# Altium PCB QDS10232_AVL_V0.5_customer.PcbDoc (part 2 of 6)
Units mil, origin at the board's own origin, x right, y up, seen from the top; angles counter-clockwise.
Board outline 3500 x 3799 mil, 6 copper layers (Top Layer, GND, INT1, PWR1, PWR2, Bottom Layer), stack 78.834 mil thick; 254 components, 204 nets, 7039 pads, 595 vias.
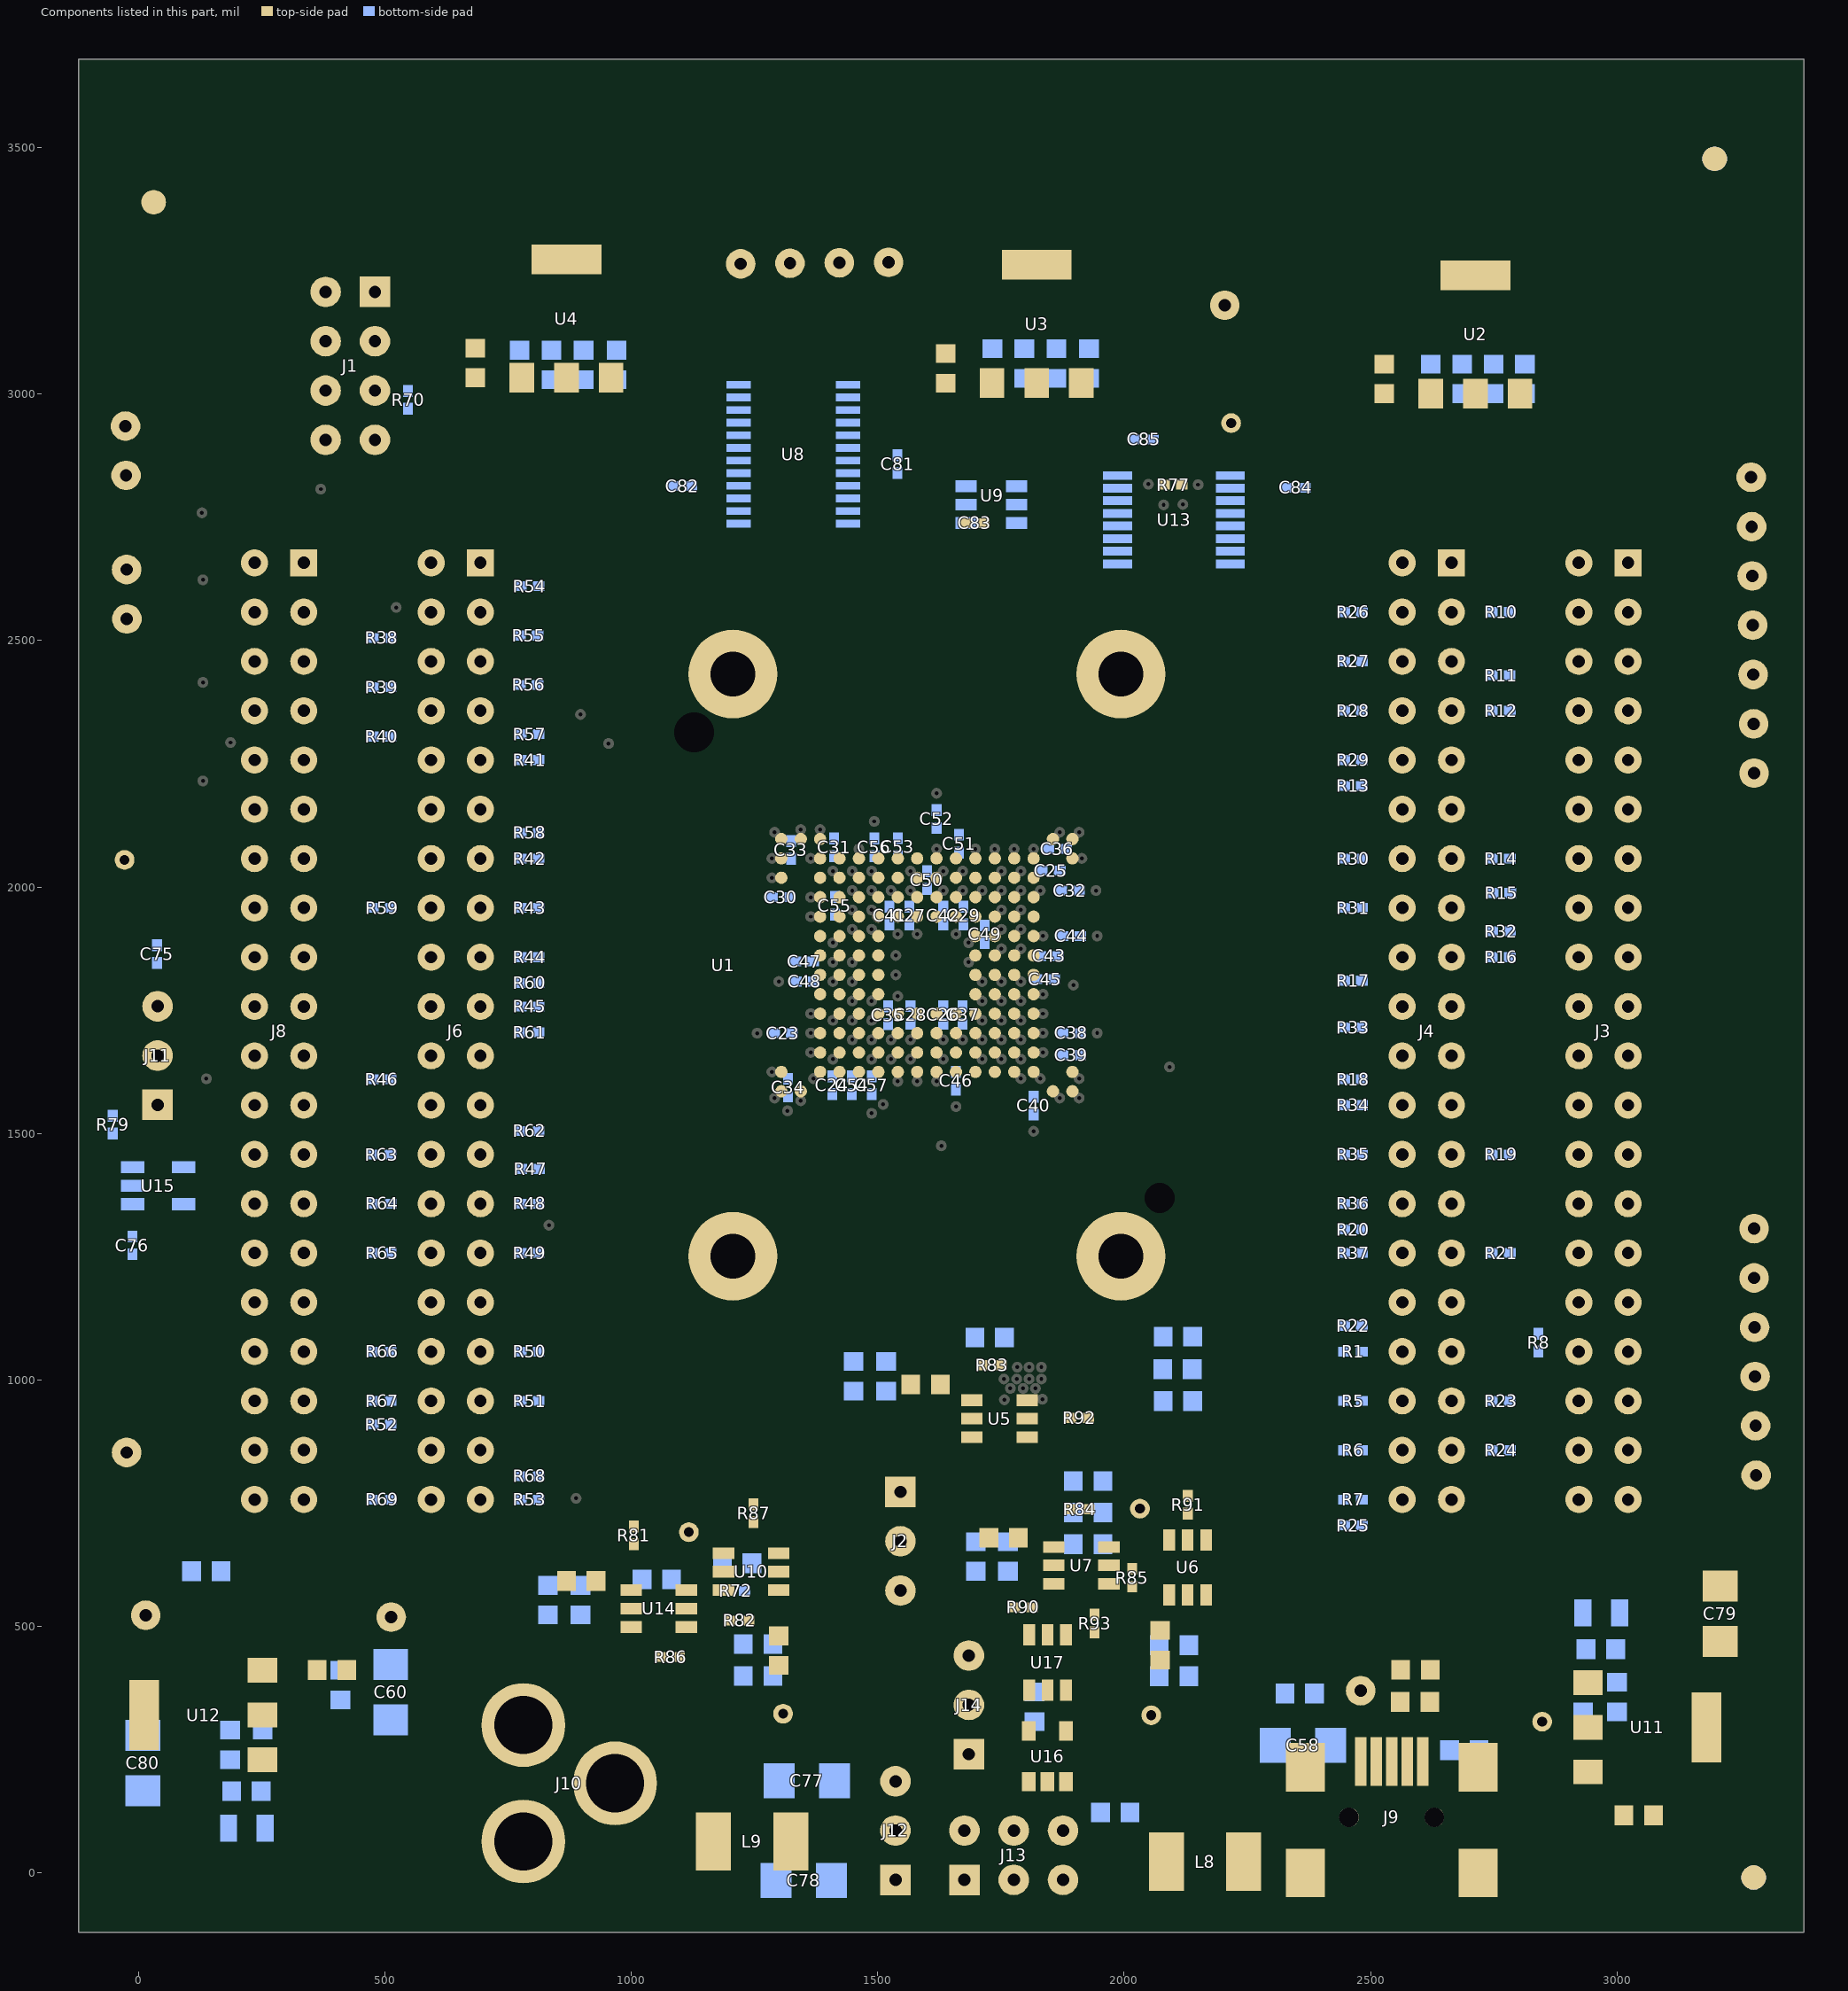
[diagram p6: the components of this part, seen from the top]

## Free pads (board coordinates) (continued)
  round 1.54 on Bottom Overlay: ""(2480.19,3556.7) ""(2480.19,3556.7) ""(2480.19,3556.7) ""(2480.19,3556.7) ""(2486.71,3556.7) ""(2486.71,3556.7) ""(2486.71,3556.7) ""(2486.71,3556.7) ""(2491.47,3556.5) ""(2491.47,3556.5) ""(2491.47,3556.5) ""(2491.47,3556.5) ""(2491.66,3570.83) ""(2491.66,3570.83) ""(2491.66,3570.83) ""(2491.66,3570.83) ""(2492,3569.15) ""(2492,3569.15) ""(2492,3569.15) ""(2492,3569.15) ""(2492.17,3555.54) ""(2492.17,3555.54) ""(2492.17,3555.54) ""(2492.17,3555.54) ""(2492.18,3557.16) ""(2492.18,3557.16) ""(2492.18,3557.16) ""(2492.18,3557.16) ""(2492.18,3572.37) ""(2492.18,3572.37) ""(2492.18,3572.37) ""(2492.18,3572.37) ""(2492.57,3568.58) ""(2492.57,3568.58) ""(2492.57,3568.58) ""(2492.57,3568.58) ""(2493.73,3555.94) ""(2493.73,3555.94) ""(2493.73,3555.94) ""(2493.73,3555.94) ""(2493.77,3554.22) ""(2493.77,3554.22) ""(2493.77,3554.22) ""(2493.77,3554.22) ""(2493.83,3568.07) ""(2493.83,3568.07) ""(2493.83,3568.07) ""(2493.83,3568.07) ""(2495.09,3568.24) ""(2495.09,3568.24) ""(2495.09,3568.24) ""(2495.09,3568.24) ""(2495.74,3554.88) ""(2495.74,3554.88) ""(2495.74,3554.88) ""(2495.74,3554.88) ""(2495.8,3574.68) ""(2495.8,3574.68) ""(2495.8,3574.68) ""(2495.8,3574.68) ""(2495.9,3571.78) ""(2495.9,3571.78) ""(2495.9,3571.78) ""(2495.9,3571.78) ""(2496.01,3568.7) ""(2496.01,3568.7) ""(2496.01,3568.7) ""(2496.01,3568.7) ""(2496.07,3573.19) ""(2496.07,3573.19) ""(2496.08,3573.19) ""(2496.08,3573.19) ""(2496.27,3553.55) ""(2496.27,3553.55) ""(2496.27,3553.55) ""(2496.27,3553.55) ""(2496.38,3570.95) ""(2496.38,3570.95) ""(2496.38,3570.95) ""(2496.38,3570.95) ""(2496.54,3569.84) ""(2496.54,3569.84) ""(2496.54,3569.84) ""(2496.54,3569.84) ""(2497.13,3574.07) ""(2497.13,3574.07) ""(2497.13,3574.07) ""(2497.13,3574.07) ""(2497.72,3554.75) ""(2497.72,3554.75) ""(2497.72,3554.75) ""(2497.72,3554.75) ""(2498.86,3553.55) ""(2498.86,3553.55) ""(2498.86,3553.55) ""(2498.86,3553.55) ""(2498.91,3574.21) ""(2498.91,3574.21) ""(2498.91,3574.21) ""(2498.91,3574.21) ""(2499.74,3574.98) ""(2499.74,3574.98) ""(2499.74,3574.98) ""(2499.74,3574.98) ""(2500.16,3555.36) ""(2500.16,3555.36) ""(2500.16,3555.36) ""(2500.16,3555.36) ""(2500.48,3573.68) ""(2500.48,3573.68) ""(2500.48,3573.68) ""(2500.48,3573.68) ""(2501.84,3572.45) ""(2501.84,3572.45) ""(2501.84,3572.45) ""(2501.84,3572.45) ""(2502.2,3557.4) ""(2502.2,3557.4) ""(2502.2,3557.4) ""(2502.2,3557.4) ""(2502.24,3554.06) ""(2502.24,3554.06) ""(2502.24,3554.06) ""(2502.24,3554.06) ""(2503.13,3574.48) ""(2503.13,3574.48) ""(2503.13,3574.48) ""(2503.13,3574.48) ""(2503.23,3570.37) ""(2503.23,3570.37) ""(2503.23,3570.37) ""(2503.23,3570.37) ""(2503.57,3560.03) ""(2503.57,3560.03) ""(2503.57,3560.03) ""(2503.57,3560.03) ""(2504.35,3563.71) ""(2504.35,3563.71) ""(2504.35,3563.71) ""(2504.35,3563.71) ""(2504.35,3566.77) ""(2504.35,3566.77) ""(2504.35,3566.77) ""(2504.35,3566.77) ""(2504.99,3554.94) ""(2504.99,3554.94) ""(2504.99,3554.94) ""(2504.99,3554.94) ""(2506.76,3556.52) ""(2506.76,3556.52) ""(2506.76,3556.52) ""(2506.76,3556.52) ""(2506.82,3572.59) ""(2506.82,3572.59) ""(2506.82,3572.59) ""(2506.82,3572.59) ""(2508.46,3558.21) ""(2508.46,3558.21) ""(2508.46,3558.21) ""(2508.46,3558.21) ""(2508.7,3570.51) ""(2508.7,3570.51) ""(2508.7,3570.51) ""(2508.7,3570.51) ""(2508.82,3570.34) ""(2508.82,3570.34) ""(2508.82,3570.34) ""(2508.82,3570.34) ""(2509.82,3560.93) ""(2509.82,3560.93) ""(2509.82,3560.93) ""(2509.82,3560.93) ""(2510.12,3564.6) ""(2510.12,3564.6) ""(2510.12,3564.6) ""(2510.12,3564.6) ""(2513.7,3554.18) ""(2513.7,3554.18) ""(2513.7,3554.56) ""(2513.7,3554.56) ""(2513.7,3554.18) ""(2513.7,3554.18) ""(2513.7,3554.56) ""(2513.7,3554.56) ""(2516.13,3556.89) ""(2516.13,3556.89) ""(2516.13,3568.58) ""(2516.13,3568.58) ""(2516.72,3571.52) ""(2516.72,3571.52) ""(2516.72,3571.52) ""(2516.72,3571.52) ""(2518,3573.35) ""(2518,3573.35) ""(2518.01,3573.35) ""(2518.01,3573.35) ""(2519.75,3574.27) ""(2519.75,3574.27) ""(2519.75,3574.27) ""(2519.75,3574.27) ""(2522.01,3557.33) ""(2522.01,3557.33) ""(2522.01,3570.41) ""(2522.01,3570.41) ""(2522.01,3557.33) ""(2522.01,3557.33) ""(2522.01,3570.41) ""(2522.01,3570.41) ""(2522.94,3572.41) ""(2522.94,3572.41) ""(2522.94,3572.41) ""(2522.94,3572.41) ""(2522.94,3574.87) ""(2522.94,3574.87) ""(2522.94,3574.87) ""(2522.94,3574.87) ""(2524.13,3554.18) ""(2524.13,3554.18) ""(2524.13,3554.18) ""(2524.13,3554.18) ""(2524.13,3555.08) ""(2524.13,3555.08) ""(2524.13,3555.08) ""(2524.13,3555.08) ""(2525.01,3573.38) ""(2525.01,3573.38) ""(2525.01,3573.38) ""(2525.01,3573.38) ""(2525.34,3574.77) ""(2525.34,3574.77) ""(2525.34,3574.77) ""(2525.34,3574.77) ""(2526.92,3573) ""(2526.92,3573) ""(2526.92,3573) ""(2526.92,3573) ""(2526.94,3554.18) ""(2526.94,3554.18) ""(2526.94,3554.18) ""(2526.94,3554.18) ""(2526.94,3555.03) ""(2526.94,3555.03) ""(2526.94,3555.03) ""(2526.94,3555.03) ""(2527.23,3573.83) ""(2527.23,3573.83) ""(2527.23,3573.83) ""(2527.23,3573.83) ""(2528.53,3572.38) ""(2528.53,3572.38) ""(2529.59,3557.36) ""(2529.59,3557.36) ""(2529.59,3557.36) ""(2529.59,3557.36) ""(2529.59,3571.17) ""(2529.59,3571.17) ""(2529.59,3571.17) ""(2529.59,3571.17) ""(2530.12,3571.48) ""(2530.12,3571.48) ""(2530.12,3571.48) ""(2530.12,3571.48) ""(2530.12,3574.66) ""(2530.12,3574.66) ""(2530.12,3574.66) ""(2530.12,3574.66) ""(2535.47,3557.17) ""(2535.47,3557.17) ""(2535.47,3557.17) ""(2535.47,3557.17) ""(2535.47,3571.11) ""(2535.47,3571.11) ""(2535.47,3571.11) ""(2535.47,3571.11) ""(2537.9,3554.18) ""(2537.9,3554.18) ""(2537.9,3554.18) ""(2537.9,3554.18) ""(2537.9,3555.16) ""(2537.9,3555.16) ""(2537.9,3555.16) ""(2537.9,3555.16) ""(2537.9,3573.34) ""(2537.9,3573.34) ""(2537.9,3573.34) ""(2537.9,3573.34) ""(2537.9,3574.66) ""(2537.9,3574.66) ""(2537.9,3574.66) ""(2537.9,3574.66) ""(2541.46,3554.18) ""(2541.46,3554.18) ""(2541.46,3554.76) ""(2541.46,3554.76) ""(2541.46,3554.18) ""(2541.46,3554.18) ""(2541.46,3554.76) ""(2541.46,3554.76) ""(2541.67,3582.88) ""(2541.67,3582.88) ""(2541.67,3583.77) ""(2541.67,3583.77) ""(2541.67,3582.88) ""(2541.67,3582.88) ""(2541.67,3583.77) ""(2541.67,3583.77) ""(2550.41,3556.3) ""(2550.41,3556.3) ""(2550.41,3556.3) ""(2550.41,3556.3) ""(2550.41,3581.09) ""(2550.41,3581.09) ""(2550.41,3581.09) ""(2550.41,3581.09) ""(2552.85,3554.18) ""(2552.85,3554.18) ""(2552.85,3554.5) ""(2552.85,3554.5) ""(2552.85,3583.1) ""(2552.85,3583.1) ""(2552.85,3583.77) ""(2552.85,3583.77) ""(2552.85,3554.18) ""(2552.85,3554.18) ""(2552.85,3554.5) ""(2552.85,3554.5) ""(2552.85,3583.1) ""(2552.85,3583.1) ""(2552.85,3583.77) ""(2552.85,3583.77) ""(2560.65,3555.44) ""(2560.65,3555.44) ""(2560.65,3555.44) ""(2560.65,3555.44) ""(2560.75,3553.91) ""(2560.75,3553.91) ""(2560.75,3553.91) ""(2560.75,3553.91) ""(2560.99,3557.24) ""(2560.99,3557.24) ""(2560.99,3557.24) ""(2560.99,3557.24) ""(2561.4,3551.62) ""(2561.4,3551.62) ""(2561.4,3551.62) ""(2561.4,3551.62) ""(2561.55,3558.55) ""(2561.55,3558.55) ""(2561.55,3558.55) ""(2561.55,3558.55) ""(2562.24,3559.32) ""(2562.24,3559.32) ""(2562.24,3559.32) ""(2562.24,3559.32) ""(2562.34,3552.12) ""(2562.34,3552.12) ""(2562.34,3552.12) ""(2562.34,3552.12) ""(2562.68,3553.7) ""(2562.68,3553.7) ""(2562.68,3553.7) ""(2562.68,3553.7) ""(2562.75,3549.22) ""(2562.75,3549.22) ""(2562.75,3549.22) ""(2562.75,3549.22) ""(2562.83,3550.79) ""(2562.83,3550.79) ""(2562.83,3550.79) ""(2562.83,3550.79) ""(2562.9,3559.89) ""(2562.9,3559.89) ""(2562.9,3559.89) ""(2562.9,3559.89) ""(2563.47,3560.11) ""(2563.47,3560.11) ""(2563.47,3560.11) ""(2563.47,3560.11) ""(2563.69,3549.68) ""(2563.69,3549.68) ""(2563.69,3549.68) ""(2563.69,3549.68) ""(2564.14,3547.73) ""(2564.14,3547.73) ""(2564.14,3547.73) ""(2564.14,3547.73) ""(2564.35,3560.06) ""(2564.35,3560.06) ""(2564.35,3560.06) ""(2564.35,3560.06) ""(2565.22,3553.82) ""(2565.22,3553.82) ""(2565.22,3553.82) ""(2565.22,3553.82) ""(2565.3,3560.06) ""(2565.3,3560.06) ""(2565.3,3560.06) ""(2565.3,3560.06) ""(2565.3,3548.18) ""(2565.3,3548.18) ""(2565.3,3548.18) ""(2565.3,3548.18) ""(2565.59,3546.59) ""(2565.59,3546.59) ""(2565.59,3546.59) ""(2565.59,3546.59) ""(2565.84,3554.2) ""(2565.84,3554.2) ""(2565.84,3554.2) ""(2565.84,3554.2) ""(2565.92,3559.73) ""(2565.92,3559.73) ""(2565.92,3559.73) ""(2565.92,3559.73) ""(2566.33,3547.32) ""(2566.33,3547.32) ""(2566.33,3547.32) ""(2566.33,3547.32) ""(2566.45,3554.71) ""(2566.45,3554.71) ""(2566.45,3554.71) ""(2566.45,3554.71) ""(2566.54,3559.38) ""(2566.54,3559.38) ""(2566.54,3559.38) ""(2566.54,3559.38) ""(2566.94,3555.24) ""(2566.94,3555.24) ""(2566.94,3555.24) ""(2566.94,3555.24) ""(2566.96,3558.89) ""(2566.96,3558.89) ""(2566.96,3558.89) ""(2566.96,3558.89) ""(2567.19,3556.05) ""(2567.19,3556.05) ""(2567.19,3556.05) ""(2567.19,3556.05) ""(2567.19,3558.27) ""(2567.19,3558.27) ""(2567.19,3558.27) ""(2567.19,3558.27) ""(2567.23,3557.1) ""(2567.23,3557.1) ""(2567.23,3557.1) ""(2567.23,3557.1) ""(2573.55,3561.66) ""(2573.55,3561.66) ""(2573.55,3561.66) ""(2573.55,3561.66) ""(2573.62,3560.15) ""(2573.62,3560.15) ""(2573.62,3560.15) ""(2573.62,3560.15) ""(2573.82,3562.96) ""(2573.82,3562.96) ""(2573.82,3562.96) ""(2573.82,3562.96) ""(2574.23,3564.06) ""(2574.23,3564.06) ""(2574.23,3564.06) ""(2574.23,3564.06) ""(2574.3,3558.29) ""(2574.3,3558.29) ""(2574.3,3558.29) ""(2574.3,3558.29) ""(2574.3,3570.39) ""(2574.3,3570.39) ""(2574.3,3570.39) ""(2574.3,3570.39) ""(2574.3,3571.49) ""(2574.3,3571.49) ""(2574.3,3571.49) ""(2574.3,3571.49) ""(2574.51,3572.52) ""(2574.51,3572.52) ""(2574.58,3569.84) ""(2574.58,3569.84) ""(2574.58,3569.84) ""(2574.58,3569.84) ""(2574.65,3564.81) ""(2574.65,3564.81) ""(2574.65,3564.81) ""(2574.65,3564.81) ""(2574.99,3569.29) ""(2574.99,3569.29) ""(2574.99,3569.29) ""(2574.99,3569.29) ""(2575.06,3557.13) ""(2575.06,3557.13) ""(2575.06,3557.13) ""(2575.06,3557.13) ""(2575.13,3573.34) ""(2575.13,3573.34) ""(2575.13,3573.34) ""(2575.13,3573.34) ""(2575.61,3565.64) ""(2575.61,3565.64) ""(2575.61,3565.64) ""(2575.61,3565.64) ""(2575.95,3568.74) ""(2575.95,3568.74) ""(2576.02,3574.09) ""(2576.02,3574.09) ""(2576.09,3556.17) ""(2576.09,3556.17) ""(2576.09,3556.17) ""(2576.09,3556.17) ""(2576.85,3568.4) ""(2576.85,3568.4) ""(2576.85,3568.4) ""(2576.85,3568.4) ""(2577.33,3574.85) ""(2577.33,3574.85) ""(2577.33,3574.85) ""(2577.33,3574.85) ""(2577.4,3566.46) ""(2577.4,3566.46) ""(2577.4,3566.46) ""(2577.4,3566.46) ""(2577.74,3555.14) ""(2577.74,3555.14) ""(2577.74,3555.14) ""(2577.74,3555.14) ""(2578.15,3575.12) ""(2578.15,3575.12) ""(2578.15,3575.12) ""(2578.15,3575.12) ""(2579.04,3554.45) ""(2579.04,3554.45) ""(2579.04,3554.45) ""(2579.04,3554.45) ""(2579.25,3567.22) ""(2579.25,3567.22) ""(2579.25,3567.22) ""(2579.25,3567.22) ""(2579.32,3558.79) ""(2579.32,3558.79) ""(2579.32,3558.79) ""(2579.32,3558.79) ""(2579.32,3568.59) ""(2579.32,3568.59) ""(2579.32,3568.59) ""(2579.32,3568.59) ""(2579.46,3558.1) ""(2579.46,3558.1) ""(2579.46,3559.61) ""(2579.46,3559.61) ""(2579.46,3558.1) ""(2579.46,3558.1) ""(2579.46,3559.61) ""(2579.46,3559.61) ""(2579.66,3557.62) ""(2579.66,3557.62) ""(2579.66,3557.62) ""(2579.66,3557.62) ""(2579.73,3560.16) ""(2579.73,3560.16) ""(2579.73,3560.16) ""(2579.73,3560.16) ""(2579.73,3575.4) ""(2579.73,3575.4) ""(2579.73,3575.4) ""(2579.73,3575.4) ""(2579.87,3569.07) ""(2579.87,3569.07) ""(2579.87,3569.07) ""(2579.87,3569.07) ""(2579.87,3571.27) ""(2579.87,3571.27) ""(2579.87,3571.27) ""(2579.87,3571.27) ""(2579.87,3571.47) ""(2579.87,3571.47) ""(2579.87,3571.47) ""(2579.87,3571.47) ""(2580.01,3570.79) ""(2580.01,3570.79) ""(2580.01,3570.79) ""(2580.01,3570.79) ""(2580.01,3571.88) ""(2580.01,3571.88) ""(2580.01,3571.88) ""(2580.01,3571.88) ""(2580.07,3569.62) ""(2580.07,3569.62) ""(2580.07,3569.62) ""(2580.07,3569.62) ""(2580.14,3570.3) ""(2580.14,3570.3) ""(2580.14,3570.3) ""(2580.14,3570.3) ""(2580.14,3571.95) ""(2580.14,3571.95) ""(2580.14,3571.95) ""(2580.14,3571.95) ""(2580.28,3557.14) ""(2580.28,3557.14) ""(2580.28,3557.14) ""(2580.28,3557.14) ""(2580.42,3560.64) ""(2580.42,3560.64) ""(2580.42,3560.64) ""(2580.42,3560.64) ""(2580.49,3572.3) ""(2580.49,3572.3) ""(2580.49,3572.3) ""(2580.49,3572.3) ""(2580.69,3567.7) ""(2580.69,3567.7) ""(2580.69,3567.7) ""(2580.69,3567.7) ""(2580.9,3556.8) ""(2580.9,3556.8) ""(2580.9,3556.8) ""(2580.9,3556.8) ""(2581.24,3561.05) ""(2581.24,3561.05) ""(2581.24,3572.5) ""(2581.24,3572.5) ""(2581.52,3575.33) ""(2581.52,3575.33) ""(2581.52,3575.33) ""(2581.52,3575.33) ""(2582.14,3572.57) ""(2582.14,3572.57) ""(2582.14,3572.57) ""(2582.14,3572.57) ""(2582.2,3568.25) ""(2582.2,3568.25) ""(2582.2,3568.25) ""(2582.2,3568.25) ""(2582.27,3556.38) ""(2582.27,3556.38) ""(2582.27,3556.38) ""(2582.27,3556.38) ""(2582.96,3553.97) ""(2582.96,3553.97) ""(2582.96,3553.97) ""(2582.96,3553.97) ""(2583.03,3572.57) ""(2583.03,3572.57) ""(2583.03,3572.57) ""(2583.03,3572.57) ""(2583.17,3575.12) ""(2583.17,3575.12) ""(2583.17,3575.12) ""(2583.17,3575.12) ""(2583.37,3556.25) ""(2583.37,3556.25) ""(2583.37,3568.73) ""(2583.37,3568.73) ""(2583.85,3572.16) ""(2583.85,3572.16) ""(2583.85,3572.16) ""(2583.85,3572.16) ""(2584.06,3569) ""(2584.06,3569) ""(2584.06,3569) ""(2584.06,3569) ""(2584.26,3571.68) ""(2584.26,3571.68) ""(2584.26,3571.68) ""(2584.26,3571.68) ""(2584.4,3569.48) ""(2584.4,3569.48) ""(2584.4,3569.48) ""(2584.4,3569.48) ""(2584.47,3556.32) ""(2584.47,3556.32) ""(2584.47,3556.32) ""(2584.47,3556.32) ""(2584.54,3570.03) ""(2584.54,3570.03) ""(2584.54,3570.03) ""(2584.54,3570.03) ""(2584.54,3570.65) ""(2584.54,3570.65) ""(2584.54,3570.65) ""(2584.54,3570.65) ""(2584.81,3559.41) ""(2584.81,3559.41) ""(2584.81,3559.41) ""(2584.81,3559.41) ""(2584.88,3558.58) ""(2584.88,3558.58) ""(2585.02,3560.16) ""(2585.02,3560.16) ""(2585.02,3560.16) ""(2585.02,3560.16) ""(2585.09,3558.17) ""(2585.09,3558.17) ""(2585.09,3558.17) ""(2585.09,3558.17) ""(2585.09,3574.64) ""(2585.09,3574.64) ""(2585.09,3574.64) ""(2585.09,3574.64) ""(2585.23,3554.11) ""(2585.23,3554.11) ""(2585.23,3554.11) ""(2585.23,3554.11) ""(2585.29,3556.45) ""(2585.29,3556.45) ""(2585.29,3558.1) ""(2585.29,3558.1) ""(2585.3,3556.45) ""(2585.3,3556.45) ""(2585.3,3558.1) ""(2585.3,3558.1) ""(2585.71,3557.69) ""(2585.71,3557.69) ""(2585.71,3557.69) ""(2585.71,3557.69) ""(2585.78,3556.8) ""(2585.78,3556.8) ""(2585.78,3556.8) ""(2585.78,3556.8) ""(2585.84,3557.14) ""(2585.84,3557.14) ""(2585.84,3557.14) ""(2585.84,3557.14) ""(2585.98,3560.85) ""(2585.98,3560.85) ""(2585.98,3560.85) ""(2585.98,3560.85) ""(2586.6,3573.96) ""(2586.6,3573.96) ""(2586.6,3573.96) ""(2586.6,3573.96) ""(2586.81,3561.26) ""(2586.81,3561.26) ""(2586.81,3561.26) ""(2586.81,3561.26) ""(2586.94,3554.38) ""(2586.94,3554.38) ""(2586.94,3554.38) ""(2586.94,3554.38) ""(2587.22,3563.59) ""(2587.22,3563.59) ""(2587.22,3563.59) ""(2587.22,3563.59) ""(2587.63,3561.33) ""(2587.63,3561.33) ""(2587.63,3561.33) ""(2587.63,3561.33) ""(2587.84,3573.2) ""(2587.84,3573.2) ""(2587.84,3573.2) ""(2587.84,3573.2) ""(2588.11,3554.72) ""(2588.11,3554.72) ""(2588.11,3554.72) ""(2588.11,3554.72) ""(2588.39,3564.42) ""(2588.39,3564.42) ""(2588.39,3564.42) ""(2588.39,3564.42) ""(2588.73,3572.31) ""(2588.73,3572.31) ""(2588.73,3572.31) ""(2588.73,3572.31) ""(2589,3561.19) ""(2589,3561.19) ""(2589,3561.19) ""(2589,3561.19) ""(2589.28,3565.24) ""(2589.28,3565.24) ""(2589.28,3565.24) ""(2589.28,3565.24) ""(2589.35,3555.48) ""(2589.35,3555.48) ""(2589.35,3555.48) ""(2589.35,3555.48) ""(2589.35,3571.42) ""(2589.35,3571.42) ""(2589.35,3571.42) ""(2589.35,3571.42) ""(2589.62,3560.78) ""(2589.62,3560.78) ""(2589.62,3560.78) ""(2589.62,3560.78) ""(2589.9,3556.11) ""(2589.9,3556.11) ""(2589.9,3566.2) ""(2589.9,3566.2) ""(2589.9,3570.59) ""(2589.9,3570.59) ""(2589.9,3556.11) ""(2589.9,3556.11) ""(2589.9,3566.2) ""(2589.9,3566.2) ""(2589.9,3570.59) ""(2589.9,3570.59) ""(2590.17,3569.77) ""(2590.17,3569.77) ""(2590.17,3569.77) ""(2590.17,3569.77) ""(2590.24,3567.3) ""(2590.24,3567.3) ""(2590.24,3567.3) ""(2590.24,3567.3) ""(2590.31,3568.67) ""(2590.31,3568.67) ""(2590.31,3568.67) ""(2590.31,3568.67) ""(2590.38,3556.93) ""(2590.38,3556.93) ""(2590.38,3556.93) ""(2590.38,3556.93) ""(2590.38,3560.16) ""(2590.38,3560.16) ""(2590.38,3560.16) ""(2590.38,3560.16) ""(2590.65,3559.47) ""(2590.65,3559.47) ""(2590.65,3559.47) ""(2590.65,3559.47) ""(2590.72,3557.83) ""(2590.72,3557.83) ""(2590.72,3557.83) ""(2590.72,3557.83) ""(2590.79,3558.72) ""(2590.79,3558.72) ""(2590.79,3558.72) ""(2590.79,3558.72) ""(2593.72,3565.13) ""(2593.72,3566.01) ""(2593.72,3566.01) ""(2593.72,3565.13) ""(2593.72,3565.13) ""(2593.72,3565.13) ""(2593.72,3566.01) ""(2593.72,3566.01) ""(2593.72,3565.13) ""(2593.93,3567.59) ""(2593.93,3567.59) ""(2593.93,3567.59) ""(2593.93,3567.59) ""(2594,3557.35) ""(2594,3557.35) ""(2594,3557.35) ""(2594,3557.35) ""(2594,3557.35) ""(2594.08,3558.45) ""(2594.08,3558.45) ""(2594.08,3558.45) ""(2594.08,3558.45) ""(2594.08,3558.45) ""(2594.13,3568.75) ""(2594.13,3568.75) ""(2594.13,3568.75) ""(2594.13,3568.75) ""(2594.49,3564.36) ""(2594.49,3564.36) ""(2594.49,3564.36) ""(2594.49,3564.36) ""(2594.49,3564.36) ""(2594.88,3559.12) ""(2594.88,3559.12) ""(2594.88,3559.12) ""(2594.88,3559.12) ""(2594.88,3559.12) ""(2594.89,3556.33) ""(2594.89,3556.33) ""(2594.89,3556.33) ""(2594.89,3556.33) ""(2594.89,3570.4) ""(2594.89,3570.4) ""(2594.89,3570.4) ""(2594.89,3570.4) ""(2595.78,3555.44) ""(2595.78,3555.44) ""(2595.78,3571.84) ""(2595.78,3571.84) ""(2595.78,3555.44) ""(2595.78,3555.44) ""(2595.78,3571.84) ""(2595.78,3571.84) ""(2595.92,3559.07) ""(2595.92,3559.07) ""(2595.92,3559.07) ""(2595.92,3559.07) ""(2595.92,3559.07) ""(2596.47,3558.53) ""(2596.47,3558.53) ""(2596.81,3572.87) ""(2596.81,3572.87) ""(2596.81,3572.87) ""(2596.81,3572.87) ""(2597.36,3554.48) ""(2597.36,3554.48) ""(2597.36,3554.48) ""(2597.36,3554.48) ""(2597.57,3557.7) ""(2597.57,3557.7) ""(2597.57,3557.7) ""(2597.57,3557.7) ""(2598.12,3573.9) ""(2598.12,3573.9) ""(2598.12,3573.9) ""(2598.12,3573.9) ""(2598.46,3554) ""(2598.46,3554) ""(2598.46,3554) ""(2598.46,3554) ""(2598.53,3557.08) ""(2598.53,3557.08) ""(2598.53,3557.08) ""(2598.53,3557.08) ""(2599.28,3574.66) ""(2599.28,3574.66) ""(2599.28,3574.66) ""(2599.28,3574.66) ""(2599.7,3556.6) ""(2599.7,3556.6) ""(2599.7,3556.6) ""(2599.7,3556.6) ""(2600.18,3567.46) ""(2600.18,3568.07) ""(2600.18,3568.07) ""(2600.18,3567.46) ""(2600.18,3567.46) ""(2600.18,3567.46) ""(2600.18,3567.46) ""(2600.18,3568.07) ""(2600.18,3568.07) ""(2600.32,3569.51) ""(2600.32,3569.51) ""(2600.32,3569.51) ""(2600.32,3569.51) ""(2600.52,3570.61) ""(2600.52,3570.61) ""(2600.52,3570.61) ""(2600.52,3570.61) ""(2600.65,3575.14) ""(2600.65,3575.14) ""(2600.65,3575.14) ""(2600.65,3575.14) ""(2600.73,3553.79) ""(2600.73,3553.79) ""(2600.73,3553.79) ""(2600.73,3553.79) ""(2600.87,3571.36) ""(2600.87,3571.36) ""(2600.87,3571.36) ""(2600.87,3571.36) ""(2600.95,3566.69) ""(2600.95,3566.69) ""(2600.95,3566.69) ""(2600.95,3566.69) ""(2600.95,3566.69) ""(2601,3556.47) ""(2601,3556.47) ""(2601,3556.47) ""(2601,3556.47) ""(2601.55,3572.05) ""(2601.55,3572.05) ""(2601.55,3572.05) ""(2601.55,3572.05) ""(2601.96,3556.54) ""(2601.96,3556.54) ""(2601.96,3556.54) ""(2601.96,3556.54) ""(2602.23,3575.35) ""(2602.23,3575.35) ""(2602.31,3572.32) ""(2602.31,3572.32) ""(2602.31,3572.32) ""(2602.31,3572.32) ""(2602.79,3553.79) ""(2602.79,3553.79) ""(2602.93,3556.81) ""(2602.93,3556.81) ""(2602.93,3556.81) ""(2602.93,3556.81) ""(2602.99,3572.39) ""(2602.99,3572.39) ""(2602.99,3572.39) ""(2602.99,3572.39) ""(2603.54,3575.35) ""(2603.54,3575.35) ""(2603.54,3575.35) ""(2603.54,3575.35) ""(2603.68,3557.15) ""(2603.68,3557.15) ""(2603.68,3557.15) ""(2603.68,3557.15) ""(2603.89,3572.32) ""(2603.89,3572.32) ""(2603.89,3572.32) ""(2603.89,3572.32) ""(2604.85,3558.18) ""(2604.85,3558.18) ""(2604.85,3558.18) ""(2604.85,3558.18) ""(2605.26,3554) ""(2605.26,3554) ""(2605.26,3558.8) ""(2605.26,3558.8) ""(2605.26,3554) ""(2605.26,3554) ""(2605.26,3558.8) ""(2605.26,3558.8) ""(2605.47,3571.16) ""(2605.47,3571.16) ""(2605.47,3571.16) ""(2605.47,3571.16) ""(2605.49,3566.69) ""(2605.49,3566.69) ""(2605.49,3566.69) ""(2605.49,3566.69) ""(2605.49,3566.69) ""(2605.59,3564.36) ""(2605.59,3564.36) ""(2605.59,3564.36) ""(2605.59,3564.36) ""(2605.59,3564.36) ""(2605.67,3575.21) ""(2605.67,3575.21) ""(2605.67,3575.21) ""(2605.67,3575.21) ""(2605.74,3570.47) ""(2605.74,3570.47) ""(2605.74,3570.47) ""(2605.74,3570.47) ""(2605.81,3560.24) ""(2605.81,3560.24) ""(2605.81,3560.24) ""(2605.81,3560.24) ""(2606.02,3561.07) ""(2606.02,3561.07) ""(2606.02,3561.07) ""(2606.02,3561.07) ""(2606.17,3569.09) ""(2606.17,3569.09) ""(2606.17,3569.09) ""(2606.17,3569.09) ""(2606.17,3569.09) ""(2606.2,3568.89) ""(2606.2,3568.89) ""(2606.2,3568.89) ""(2606.2,3568.89) ""(2606.2,3568.89) ""(2606.22,3562.16) ""(2606.22,3562.16) ""(2606.22,3562.16) ""(2606.22,3562.16) ""(2606.26,3567.49) ""(2606.26,3567.49) ""(2606.26,3567.49) ""(2606.26,3567.49) ""(2606.26,3567.49) ""(2606.36,3563.51) ""(2606.36,3563.51) ""(2606.36,3563.51) ""(2606.36,3563.51) ""(2606.36,3563.51) ""(2607.25,3554.61) ""(2607.25,3554.61) ""(2607.25,3554.61) ""(2607.25,3554.61) ""(2607.6,3574.31) ""(2607.6,3574.31) ""(2607.6,3574.31) ""(2607.6,3574.31) ""(2608.56,3555.23) ""(2608.56,3555.23) ""(2608.97,3573.35) ""(2608.97,3573.35) ""(2608.97,3573.35) ""(2608.97,3573.35) ""(2610.07,3572.39) ""(2610.07,3572.39) ""(2610.07,3572.39) ""(2610.07,3572.39) ""(2610.14,3556.33) ""(2610.14,3556.33) ""(2610.14,3556.33) ""(2610.14,3556.33) ""(2611.17,3571.22) ""(2611.17,3571.22) ""(2611.17,3571.22) ""(2611.17,3571.22) ""(2611.93,3569.99) ""(2611.93,3569.99) ""(2611.93,3569.99) ""(2611.93,3569.99) ""(2612.2,3559.01) ""(2612.2,3559.01) ""(2612.2,3559.01) ""(2612.2,3559.01) ""(2612.54,3568.62) ""(2612.54,3568.62) ""(2612.54,3568.62) ""(2612.54,3568.62) ""(2612.82,3560.45) ""(2612.82,3560.45) ""(2612.82,3560.45) ""(2612.82,3560.45) ""(2612.96,3567.45) ""(2612.96,3567.45) ""(2612.96,3567.45) ""(2612.96,3567.45) ""(2613.16,3562.37) ""(2613.16,3562.37) ""(2613.16,3562.37) ""(2613.16,3562.37) ""(2613.23,3566.01) ""(2613.23,3566.01) ""(2613.23,3566.01) ""(2613.23,3566.01) ""(2613.3,3564.09) ""(2613.3,3564.09) ""(2613.3,3564.09) ""(2613.3,3564.09) ""(2615.83,3557.63) ""(2615.83,3557.63) ""(2615.83,3557.63) ""(2615.83,3557.63) ""(2615.83,3557.63) ""(2615.85,3556.57) ""(2615.85,3556.57) ""(2615.85,3556.57) ""(2615.85,3556.57) ""(2615.85,3556.57) ""(2616.13,3569.71) ""(2616.13,3569.71) ""(2616.13,3569.71) ""(2616.13,3569.71) ""(2616.27,3571.42) ""(2616.27,3571.42) ""(2616.27,3571.42) ""(2616.27,3571.42) ""(2616.41,3568.68) ""(2616.41,3568.68) ""(2616.41,3568.68) ""(2616.41,3568.68) ""(2616.61,3555.77) ""(2616.61,3555.77) ""(2616.61,3555.77) ""(2616.61,3555.77) ""(2616.63,3558.5) ""(2616.63,3558.5) ""(2616.63,3558.5) ""(2616.63,3558.5) ""(2616.63,3558.5) ""(2616.68,3572.25) ""(2616.68,3572.25) ""(2616.68,3572.25) ""(2616.68,3572.25) ""(2617.09,3567.79) ""(2617.09,3567.79) ""(2617.09,3567.79) ""(2617.09,3567.79) ""(2617.3,3573.14) ""(2617.3,3573.14) ""(2617.3,3573.14) ""(2617.3,3573.14) ""(2617.51,3555.16) ""(2617.51,3555.16) ""(2617.51,3555.16) ""(2617.51,3555.16) ""(2617.69,3558.58) ""(2617.69,3558.58) ""(2617.69,3558.58) ""(2617.69,3558.58) ""(2617.69,3558.58) ""(2617.85,3567.44) ""(2617.85,3567.44) ""(2617.85,3567.44) ""(2617.85,3567.44) ""(2618.19,3573.89) ""(2618.19,3573.89) ""(2618.19,3573.89) ""(2618.19,3573.89) ""(2618.26,3558.11) ""(2618.26,3558.11) ""(2618.26,3558.11) ""(2618.26,3558.11) ""(2618.61,3567.17) ""(2618.61,3567.17) ""(2618.61,3567.17) ""(2618.61,3567.17) ""(2618.81,3554.47) ""(2618.81,3554.47) ""(2618.81,3554.47) ""(2618.81,3554.47) ""(2619.02,3574.44) ""(2619.02,3574.44) ""(2619.02,3574.44) ""(2619.02,3574.44) ""(2619.36,3557.42) ""(2619.36,3557.42) ""(2619.36,3557.42) ""(2619.36,3557.42) ""(2619.57,3567.03) ""(2619.57,3567.03) ""(2619.57,3567.03) ""(2619.57,3567.03) ""(2619.84,3554.2) ""(2619.84,3554.2) ""(2619.84,3554.2) ""(2619.84,3554.2) ""(2620.25,3574.79) ""(2620.25,3574.79) ""(2620.25,3574.79) ""(2620.25,3574.79) ""(2620.49,3567.1) ""(2620.49,3567.1) ""(2620.49,3567.1) ""(2620.49,3567.1) ""(2620.72,3567.2) ""(2620.72,3567.2) ""(2620.72,3567.2) ""(2620.72,3567.2) ""(2620.87,3571.32) ""(2620.87,3571.32) ""(2620.87,3571.32) ""(2620.87,3571.32) ""(2620.91,3571.12) ""(2620.91,3571.12) ""(2620.91,3571.12) ""(2620.91,3571.12) ""(2620.94,3556.73) ""(2620.94,3556.73) ""(2620.94,3556.73) ""(2620.94,3556.73) ""(2620.94,3571.66) ""(2620.94,3571.66) ""(2620.94,3571.66) ""(2620.94,3571.66) ""(2620.99,3570.94) ""(2620.99,3570.94) ""(2620.99,3570.94) ""(2620.99,3570.94) ""(2621.04,3571.85) ""(2621.04,3571.85) ""(2621.04,3571.85) ""(2621.04,3571.85) ""(2621.06,3567.5) ""(2621.06,3567.5) ""(2621.06,3567.5) ""(2621.06,3567.5) ""(2621.08,3554.13) ""(2621.08,3554.13) ""(2621.08,3554.13) ""(2621.08,3554.13) ""(2621.16,3570.77) ""(2621.16,3570.77) ""(2621.16,3570.77) ""(2621.16,3570.77) ""(2621.22,3572.04) ""(2621.22,3572.04) ""(2621.22,3572.04) ""(2621.22,3572.04) ""(2621.26,3567.79) ""(2621.26,3567.79) ""(2621.26,3567.79) ""(2621.26,3567.79) ""(2621.28,3570.63) ""(2621.28,3570.63) ""(2621.28,3570.63) ""(2621.28,3570.63) ""(2621.45,3570.38) ""(2621.45,3570.38) ""(2621.45,3570.38) ""(2621.45,3570.38) ""(2621.49,3568.13) ""(2621.49,3568.13) ""(2621.49,3568.13) ""(2621.49,3568.13) ""(2621.6,3570.1) ""(2621.6,3570.1) ""(2621.6,3570.1) ""(2621.6,3570.1) ""(2621.7,3568.75) ""(2621.7,3568.75) ""(2621.7,3568.75) ""(2621.7,3568.75) ""(2621.7,3574.99) ""(2621.7,3574.99) ""(2621.7,3574.99) ""(2621.7,3574.99) ""(2621.72,3569.67) ""(2621.72,3569.67) ""(2621.72,3569.67) ""(2621.72,3569.67) ""(2621.73,3569.2) ""(2621.73,3569.2) ""(2621.73,3569.2) ""(2621.73,3569.2) ""(2622.25,3556.6) ""(2622.25,3556.6) ""(2622.25,3556.6) ""(2622.25,3556.6) ""(2622.45,3572.45) ""(2622.45,3572.45) ""(2622.45,3572.45) ""(2622.45,3572.45) ""(2623.07,3556.73) ""(2623.07,3556.73) ""(2623.07,3556.73) ""(2623.07,3556.73) ""(2623.35,3572.38) ""(2623.35,3572.38) ""(2623.35,3572.38) ""(2623.35,3572.38) ""(2623.48,3554.13) ""(2623.48,3554.13) ""(2623.48,3574.99) ""(2623.48,3574.99) ""(2623.48,3554.13) ""(2623.48,3554.13) ""(2623.48,3574.99) ""(2623.48,3574.99) ""(2623.96,3556.94) ""(2623.96,3556.94) ""(2623.96,3556.94) ""(2623.96,3556.94) ""(2624.51,3572.04) ""(2624.51,3572.04) ""(2624.51,3572.04) ""(2624.51,3572.04) ""(2624.65,3557.42) ""(2624.65,3557.42) ""(2624.65,3557.42) ""(2624.65,3557.42) ""(2624.97,3554.09) ""(2624.97,3554.09) ""(2624.97,3554.09) ""(2624.97,3554.09) ""(2625.41,3557.97) ""(2625.41,3557.97) ""(2625.41,3574.85) ""(2625.41,3574.85) ""(2625.41,3557.97) ""(2625.41,3557.97) ""(2625.41,3574.85) ""(2625.41,3574.85) ""(2625.47,3571.29) ""(2625.47,3571.29) ""(2625.47,3571.29) ""(2625.47,3571.29) ""(2625.9,3554.16) ""(2625.9,3554.16) ""(2626.02,3558.79) ""(2626.02,3558.79) ""(2626.02,3558.79) ""(2626.02,3558.79) ""(2626.23,3570.19) ""(2626.23,3570.19) ""(2626.23,3570.19) ""(2626.23,3570.19) ""(2626.51,3559.76) ""(2626.51,3559.76) ""(2626.51,3559.76) ""(2626.51,3559.76) ""(2626.53,3554.31) ""(2626.53,3554.31) ""(2626.53,3554.31) ""(2626.53,3554.31) ""(2626.85,3568.75) ""(2626.85,3568.75) ""(2626.85,3568.75) ""(2626.85,3568.75) ""(2626.92,3561.06) ""(2626.92,3561.06) ""(2626.92,3561.06) ""(2626.92,3561.06) ""(2627.05,3567.65) ""(2627.05,3567.65) ""(2627.05,3567.65) ""(2627.05,3567.65) ""(2627.19,3566.28) ""(2627.19,3566.28) ""(2627.19,3566.28) ""(2627.19,3566.28) ""(2627.26,3562.64) ""(2627.26,3562.64) ""(2627.26,3562.64) ""(2627.26,3562.64) ""(2627.33,3564.35) ""(2627.33,3564.35) ""(2627.33,3564.35) ""(2627.33,3564.35) ""(2627.43,3554.63) ""(2627.43,3554.63) ""(2627.43,3554.63) ""(2627.43,3554.63) ""(2627.47,3574.44) ""(2627.47,3574.44) ""(2627.47,3574.44) ""(2627.47,3574.44) ""(2628.24,3555.08) ""(2628.24,3555.08) ""(2628.24,3555.08) ""(2628.24,3555.08) ""(2628.92,3555.5) ""(2628.92,3555.5) ""(2628.92,3555.5) ""(2628.92,3555.5) ""(2629.05,3573.69) ""(2629.05,3573.69) ""(2629.05,3573.69) ""(2629.05,3573.69) ""(2629.59,3556.04) ""(2629.59,3556.04) ""(2629.59,3556.04) ""(2629.59,3556.04) ""(2630.35,3572.59) ""(2630.35,3572.59) ""(2630.35,3572.59) ""(2630.35,3572.59) ""(2630.48,3556.74) ""(2630.48,3556.74) ""(2630.48,3556.74) ""(2630.48,3556.74) ""(2631.03,3557.26) ""(2631.03,3557.26) ""(2631.03,3557.26) ""(2631.03,3557.26) ""(2631.45,3557.7) ""(2631.45,3557.7) ""(2631.46,3557.7) ""(2631.46,3557.7) ""(2631.86,3571.29) ""(2631.86,3571.29) ""(2631.86,3571.29) ""(2631.86,3571.29) ""(2632,3558.38) ""(2632,3558.38) ""(2632,3558.38) ""(2632,3558.38) ""(2632.76,3569.91) ""(2632.76,3569.91) ""(2632.76,3569.91) ""(2632.76,3569.91) ""(2632.96,3560.17) ""(2632.96,3560.17) ""(2632.96,3560.17) ""(2632.96,3560.17) ""(2633.44,3568.27) ""(2633.44,3568.27) ""(2633.44,3568.27) ""(2633.44,3568.27) ""(2633.65,3562.02) ""(2633.65,3562.02) ""(2633.65,3562.02) ""(2633.65,3562.02) ""(2633.79,3566.76) ""(2633.79,3566.76) ""(2633.79,3566.76) ""(2633.79,3566.76) ""(2633.86,3563.8) ""(2633.86,3563.8) ""(2633.86,3563.8) ""(2633.86,3563.8) ""(2633.99,3565.11) ""(2633.99,3565.11) ""(2633.99,3565.11) ""(2633.99,3565.11) ""(2635.94,3555.17) ""(2635.94,3555.17) ""(2635.94,3555.17) ""(2635.94,3555.17) ""(2635.94,3555.17) ""(2635.94,3556.1) ""(2635.94,3556.1) ""(2635.94,3556.1) ""(2635.94,3556.1) ""(2635.94,3556.1) ""(2637.5,3556.87) ""(2637.5,3556.87) ""(2637.5,3556.87) ""(2637.5,3556.87) ""(2637.5,3556.87) ""(2638.14,3581.73) ""(2638.28,3557.64) ""(2638.28,3557.64) ""(2638.28,3557.64) ""(2638.28,3557.64) ""(2638.28,3557.64) ""(2638.28,3573.96) ""(2638.28,3573.96) ""(2638.28,3573.96) ""(2638.28,3573.96) ""(2638.28,3573.96) ""(2639.05,3574.73) ""(2639.05,3574.73) ""(2639.05,3574.73) ""(2639.05,3574.73) ""(2639.05,3574.73) ""(2644.32,3557.64) ""(2644.32,3557.64) ""(2644.32,3571) ""(2644.32,3571) ""(2644.32,3557.64) ""(2644.32,3557.64) ""(2644.32,3557.64) ""(2644.32,3571) ""(2644.32,3571) ""(2644.32,3571) ""(2645.09,3556.87) ""(2645.09,3556.87) ""(2645.09,3556.87) ""(2645.09,3556.87) ""(2645.09,3556.87) ""(2645.09,3571.77) ""(2645.09,3571.77) ""(2645.09,3571.77) ""(2645.09,3571.77) ""(2645.09,3571.77) ""(2645.42,3581.73) ""(2646.09,3554.4) ""(2646.09,3554.4) ""(2646.09,3556.87) ""(2646.09,3556.87) ""(2646.09,3571.77) ""(2646.09,3571.77) ""(2646.09,3574.73) ""(2646.09,3574.73) ""(2646.86,3555.17) ""(2646.86,3555.17) ""(2646.86,3555.17) ""(2646.86,3555.17) ""(2646.86,3555.17) ""(2646.86,3556.1) ""(2646.86,3556.1) ""(2646.86,3556.1) ""(2646.86,3556.1) ""(2646.86,3556.1) ""(2646.86,3572.54) ""(2646.86,3572.54) ""(2646.86,3572.54) ""(2646.86,3572.54) ""(2646.86,3572.54) ""(2646.86,3573.96) ""(2646.86,3573.96) ""(2646.86,3573.96) ""(2646.86,3573.96) ""(2646.86,3573.96) ""(2650.93,3572.47) ""(2650.93,3572.47) ""(2650.93,3573.96) ""(2650.93,3573.96) ""(2650.93,3572.47) ""(2650.93,3572.47) ""(2650.93,3572.47) ""(2650.93,3573.96) ""(2650.93,3573.96) ""(2650.93,3573.96) ""(2651.92,3571.69) ""(2651.92,3571.69) ""(2651.92,3571.69) ""(2651.92,3571.69) ""(2651.92,3571.69) ""(2652.63,3571.24) ""(2652.63,3571.24) ""(2652.63,3571.24) ""(2652.63,3571.24) ""(2652.63,3571.24) ""(2655.59,3570.61) ""(2655.59,3570.61) ""(2655.59,3570.61) ""(2655.59,3570.61) ""(2655.59,3570.61) ""(2656.3,3571.69) ""(2656.3,3571.69) ""(2656.3,3571.69) ""(2656.3,3571.69) ""(2656.3,3571.69) ""(2657.3,3571.69) ""(2657.3,3571.69) ""(2657.3,3571.69) ""(2657.3,3571.69) ""(2657.3,3571.69) ""(2657.3,3574.73) ""(2657.3,3574.73) ""(2657.3,3574.73) ""(2657.3,3574.73) ""(2657.3,3574.73) ""(2658.07,3572.47) ""(2658.07,3572.47) ""(2658.07,3573.96) ""(2658.07,3573.96) ""(2658.07,3572.47) ""(2658.07,3572.47) ""(2658.07,3572.47) ""(2658.07,3573.96) ""(2658.07,3573.96) ""(2658.07,3573.96) ""(2659.05,3562.98) ""(2659.05,3562.98) ""(2659.05,3562.98) ""(2659.05,3562.98) ""(2659.05,3562.98) ""(2660.07,3554.85) ""(2660.07,3554.85) ""(2660.07,3554.85) ""(2660.07,3554.85) ""(2660.07,3554.85) ""(2660.46,3562.98) ""(2660.46,3562.98) ""(2660.46,3562.98) ""(2660.46,3562.98) ""(2660.46,3562.98) ""(2660.77,3554.4) ""(2660.77,3554.4) ""(2660.77,3554.4) ""(2660.77,3554.4) ""(2660.77,3554.4) ""(2661.71,3572.47) ""(2661.71,3572.47) ""(2661.71,3573.96) ""(2661.71,3573.96) ""(2661.71,3572.47) ""(2661.71,3572.47) ""(2661.71,3572.47) ""(2661.71,3573.96) ""(2661.71,3573.96) ""(2661.71,3573.96) ""(2662.48,3571.69) ""(2662.48,3571.69) ""(2662.48,3571.69) ""(2662.48,3571.69) ""(2662.48,3571.69) ""(2662.48,3574.73) ""(2662.48,3574.73) ""(2662.48,3574.73) ""(2662.48,3574.73) ""(2662.48,3574.73) ""(2662.66,3554.4) ""(2662.66,3554.4) ""(2662.66,3554.4) ""(2662.66,3554.4) ""(2662.66,3554.4) ""(2663.22,3571.69) ""(2663.22,3571.69) ""(2663.22,3571.69) ""(2663.22,3571.69) ""(2663.22,3571.69) ""(2663.36,3554.85) ""(2663.36,3554.85) ""(2663.36,3554.85) ""(2663.36,3554.85) ""(2663.36,3554.85) ""(2663.92,3570.61) ""(2663.92,3570.61) ""(2663.92,3570.61) ""(2663.92,3570.61) ""(2670.8,3571.24) ""(2670.8,3571.24) ""(2670.8,3571.24) ""(2670.8,3571.24) ""(2670.8,3571.24) ""(2671.5,3571.69) ""(2672.14,3571.69) ""(2672.14,3571.69) ""(2672.14,3571.69) ""(2672.14,3571.69) ""(2672.14,3571.69) ""(2672.14,3574.73) ""(2672.14,3574.73) ""(2672.14,3574.73) ""(2672.14,3574.73) ""(2672.14,3574.73) ""(2672.91,3572.47) ""(2672.91,3572.47) ""(2672.91,3572.47) ""(2672.91,3572.47) ""(2672.91,3572.47) ""(2672.91,3573.96) ""(2672.91,3573.96) ""(2672.91,3573.96) ""(2672.91,3573.96) ""(2672.91,3573.96) ""(2676.75,3570.85) ""(2676.75,3570.85) ""(2676.75,3570.85) ""(2676.75,3570.85) ""(2676.75,3572.59) ""(2676.75,3572.59) ""(2676.75,3572.59) ""(2676.75,3572.59) ""(2677.02,3569.85) ""(2677.02,3569.85) ""(2677.02,3569.85) ""(2677.02,3569.85) ""(2677.16,3573.66) ""(2677.16,3573.66) ""(2677.16,3573.66) ""(2677.16,3573.66) ""(2677.49,3569.04) ""(2677.49,3569.04) ""(2677.49,3569.04) ""(2677.49,3569.04) ""(2677.62,3574.39) ""(2677.62,3574.39) ""(2677.62,3574.39) ""(2677.62,3574.39) ""(2678.36,3568.37) ""(2678.36,3568.37) ""(2678.36,3568.37) ""(2678.36,3568.37) ""(2678.43,3574.79) ""(2678.43,3574.79) ""(2678.43,3574.79) ""(2678.43,3574.79) ""(2679.23,3568.11) ""(2679.23,3568.11) ""(2679.23,3568.11) ""(2679.23,3568.11) ""(2679.37,3574.99) ""(2679.37,3574.99) ""(2679.37,3574.99) ""(2679.37,3574.99) ""(2680.24,3568.17) ""(2680.24,3568.17) ""(2680.24,3568.17) ""(2680.24,3568.17) ""(2680.44,3574.99) ""(2680.44,3574.99) ""(2680.44,3574.99) ""(2680.44,3574.99) ""(2680.7,3568.37) ""(2680.7,3568.37) ""(2680.7,3568.37) ""(2680.7,3568.37) ""(2681.31,3568.84) ""(2681.31,3568.84) ""(2681.31,3568.84) ""(2681.31,3568.84) ""(2681.64,3569.31) ""(2681.64,3569.31) ""(2681.64,3569.31) ""(2681.64,3569.31) ""(2681.71,3574.73) ""(2681.71,3574.73) ""(2681.71,3574.73) ""(2681.71,3574.73) ""(2682.04,3569.65) ""(2682.04,3569.65) ""(2682.04,3569.65) ""(2682.04,3569.65) ""(2682.31,3569.71) ""(2682.31,3569.71) ""(2682.31,3569.71) ""(2682.31,3569.71) ""(2682.58,3574.26) ""(2682.58,3574.26) ""(2682.58,3574.26) ""(2682.58,3574.26) ""(2683.05,3569.65) ""(2683.05,3569.65) ""(2683.05,3569.65) ""(2683.05,3569.65) ""(2683.25,3555.17) ""(2683.25,3555.17) ""(2683.25,3555.17) ""(2683.25,3556.29) ""(2683.25,3556.29) ""(2683.25,3556.29) ""(2683.25,3573.66) ""(2683.25,3573.66) ""(2683.25,3573.66) ""(2683.25,3573.66) ""(2683.25,3555.17) ""(2683.25,3555.17) ""(2683.25,3556.29) ""(2683.25,3556.29) ""(2683.51,3569.24) ""(2683.51,3569.24) ""(2683.51,3569.24) ""(2683.51,3569.24) ""(2683.85,3557.04) ""(2683.85,3557.04) ""(2683.85,3557.04) ""(2683.85,3557.04) ""(2683.85,3557.04) ""(2683.98,3568.64) ""(2683.98,3568.64) ""(2683.98,3568.64) ""(2683.98,3568.64) ""(2684.02,3554.4) ""(2684.02,3554.4) ""(2684.02,3554.4) ""(2684.02,3554.4) ""(2684.02,3554.4) ""(2684.45,3567.84) ""(2684.45,3567.84) ""(2684.45,3567.84) ""(2684.45,3567.84) ""(2684.85,3566.97) ""(2684.85,3566.97) ""(2684.85,3566.97) ""(2684.85,3566.97) ""(2685.12,3565.9) ""(2685.12,3565.9) ""(2685.12,3565.9) ""(2685.12,3565.9) ""(2685.32,3565.16) ""(2685.32,3565.16) ""(2685.32,3565.16) ""(2685.32,3565.16) ""(2685.39,3557.38) ""(2685.39,3557.38) ""(2685.39,3557.38) ""(2685.39,3557.38) ""(2685.39,3557.38) ""(2685.66,3564.09) ""(2685.66,3564.09) ""(2685.66,3564.09) ""(2685.66,3564.09) ""(2685.77,3563.79) ""(2685.77,3563.79) ""(2685.77,3563.79) ""(2685.77,3563.79) ""(2685.77,3563.79) ""(2686.19,3568.37) ""(2686.19,3568.37) ""(2686.19,3573.96) ""(2686.19,3568.37) ""(2686.19,3568.37) ""(2686.19,3573.96) ""(2686.19,3573.96) ""(2686.19,3573.96) ""(2686.19,3573.96) ""(2686.96,3574.73) ""(2686.96,3574.73) ""(2686.96,3574.73) ""(2686.96,3574.73) ""(2686.96,3574.73) ""(2692.22,3571.25) ""(2692.22,3571.25) ""(2692.42,3571.59) ""(2692.42,3571.59) ""(2692.42,3571.59) ""(2692.42,3571.59) ""(2692.62,3557.34) ""(2692.62,3557.34) ""(2692.62,3557.34) ""(2692.62,3557.34) ""(2692.62,3557.34) ""(2693.15,3571.99) ""(2693.15,3571.99) ""(2693.15,3571.99) ""(2693.15,3571.99) ""(2693.78,3574.73) ""(2693.78,3574.73) ""(2693.78,3574.73) ""(2693.78,3574.73) ""(2693.78,3574.73) ""(2693.79,3554.4) ""(2693.79,3554.4) ""(2693.79,3554.4) ""(2693.79,3554.4) ""(2693.79,3554.4) ""(2693.85,3572.04) ""(2693.85,3572.04) ""(2693.85,3572.04) ""(2693.85,3572.04) ""(2693.85,3572.04) ""(2693.95,3557.04) ""(2693.95,3557.04) ""(2693.95,3557.04) ""(2693.95,3557.04) ""(2693.96,3557.04) ""(2694.55,3572.81) ""(2694.55,3572.81) ""(2694.55,3572.81) ""(2694.55,3572.81) ""(2694.55,3572.81) ""(2694.55,3573.96) ""(2694.55,3573.96) ""(2694.55,3573.96) ""(2694.55,3573.96) ""(2694.55,3573.96) ""(2694.56,3555.17) ""(2694.56,3555.17) ""(2694.56,3555.17) ""(2694.56,3555.17) ""(2694.56,3555.17) ""(2694.56,3556.29) ""(2694.56,3556.29) ""(2694.56,3556.29) ""(2694.56,3556.29) ""(2694.56,3556.29) ""(2698.3,3558.38) ""(2698.3,3558.38) ""(2698.34,3557.17) ""(2698.34,3557.17) ""(2698.34,3557.17) ""(2698.34,3557.17) ""(2698.34,3557.17) ""(2698.42,3565.2) ""(2698.42,3565.2) ""(2698.42,3565.2) ""(2698.42,3565.2) ""(2698.42,3565.2) ""(2698.42,3566.46) ""(2698.42,3566.46) ""(2698.42,3566.46) ""(2698.42,3566.46) ""(2698.57,3567.25) ""(2698.57,3567.25) ""(2698.57,3567.25) ""(2698.57,3567.25) ""(2698.82,3568.03) ""(2698.82,3568.03) ""(2698.82,3568.03) ""(2698.82,3568.03) ""(2698.84,3556.8) ""(2698.84,3556.8) ""(2698.84,3556.8) ""(2698.84,3556.8) ""(2699.11,3569.04) ""(2699.11,3569.04) ""(2699.11,3569.04) ""(2699.11,3569.04) ""(2699.2,3564.43) ""(2699.2,3564.43) ""(2699.25,3559.23) ""(2699.25,3559.23) ""(2699.78,3570.78) ""(2699.78,3570.78) ""(2699.78,3570.78) ""(2699.78,3570.78) ""(2700.24,3555.8) ""(2700.24,3555.8) ""(2700.24,3555.8) ""(2700.24,3555.8) ""(2700.33,3559.19) ""(2700.33,3559.19) ""(2700.33,3559.19) ""(2700.33,3559.19) ""(2700.33,3559.19) ""(2700.78,3572.25) ""(2700.78,3572.25) ""(2700.78,3572.25) ""(2700.78,3572.25) ""(2701.32,3558.14) ""(2701.32,3558.14) ""(2701.32,3558.14) ""(2701.32,3558.14) ""(2701.58,3555.06) ""(2701.58,3555.06) ""(2701.58,3555.06) ""(2701.58,3555.06) ""(2702.39,3573.65) ""(2702.39,3573.65) ""(2702.39,3573.65) ""(2702.39,3573.65) ""(2702.52,3557.27) ""(2702.52,3557.27) ""(2702.52,3557.27) ""(2702.52,3557.27) ""(2703.06,3554.46) ""(2703.06,3554.46) ""(2703.06,3554.46) ""(2703.06,3554.46) ""(2703.52,3556.87) ""(2703.52,3556.87) ""(2703.52,3556.87) ""(2703.52,3556.87) ""(2703.59,3574.46) ""(2703.59,3574.46) ""(2703.59,3574.46) ""(2703.59,3574.46) ""(2704.39,3554.13) ""(2704.39,3554.13) ""(2704.39,3554.13) ""(2704.39,3554.13) ""(2704.59,3556.8) ""(2704.59,3556.8) ""(2704.59,3567.47) ""(2704.59,3569.04) ""(2704.59,3569.04) ""(2704.59,3556.8) ""(2704.59,3556.8) ""(2704.59,3567.47) ""(2704.59,3567.47) ""(2704.59,3567.47) ""(2704.59,3567.47) ""(2704.59,3569.04) ""(2704.59,3569.04) ""(2704.93,3570.38) ""(2704.93,3570.38) ""(2704.93,3570.38) ""(2704.93,3570.38) ""(2705.2,3574.99) ""(2705.2,3574.99) ""(2705.2,3574.99) ""(2705.2,3574.99) ""(2705.33,3571.25) ""(2705.33,3571.25) ""(2705.33,3571.25) ""(2705.33,3571.25) ""(2705.37,3566.7) ""(2705.37,3566.7) ""(2705.37,3566.7) ""(2705.37,3566.7) ""(2705.37,3566.7) ""(2706,3571.78) ""(2706,3571.78) ""(2706,3571.78) ""(2706,3571.78) ""(2706.67,3556.87) ""(2706.67,3556.87) ""(2706.67,3572.12) ""(2706.67,3572.12) ""(2706.67,3556.87) ""(2706.67,3556.87) ""(2706.67,3572.12) ""(2706.67,3572.12) ""(2706.74,3554.06) ""(2706.74,3554.06) ""(2706.74,3554.06) ""(2706.74,3554.06) ""(2707.14,3575.12) ""(2707.14,3575.12) ""(2707.14,3575.12) ""(2707.14,3575.12) ""(2707.41,3572.18) ""(2707.41,3572.18) ""(2707.41,3572.18) ""(2707.41,3572.18) ""(2708.08,3557.47) ""(2708.08,3557.47) ""(2708.08,3557.47) ""(2708.08,3557.47) ""(2708.34,3572.12) ""(2708.34,3572.12) ""(2708.34,3572.12) ""(2708.34,3572.12) ""(2708.61,3554.06) ""(2708.61,3554.06) ""(2708.61,3554.06) ""(2708.61,3554.06) ""(2708.74,3571.91) ""(2708.74,3571.91) ""(2708.74,3571.91) ""(2708.74,3571.91) ""(2709.21,3575.06) ""(2709.21,3575.06) ""(2709.21,3575.06) ""(2709.21,3575.06) ""(2709.41,3571.58) ""(2709.41,3571.58) ""(2709.41,3571.58) ""(2709.41,3571.58) ""(2709.82,3554.19) ""(2709.82,3554.19) ""(2709.82,3554.19) ""(2709.82,3554.19) ""(2710.02,3571.04) ""(2710.02,3571.04) ""(2710.02,3571.04) ""(2710.02,3571.04) ""(2710.31,3566.7) ""(2710.31,3566.7) ""(2710.31,3566.7) ""(2710.31,3566.7) ""(2710.31,3566.7) ""(2710.35,3570.51) ""(2710.35,3570.51) ""(2710.35,3570.51) ""(2710.35,3570.51) ""(2710.38,3564.43) ""(2710.38,3564.43) ""(2710.38,3564.43) ""(2710.38,3564.43) ""(2710.38,3564.43) ""(2710.54,3569.99) ""(2710.54,3569.99) ""(2710.54,3569.99) ""(2710.54,3569.99) ""(2710.69,3560.55) ""(2710.69,3560.55) ""(2710.69,3560.55) ""(2710.69,3560.55) ""(2710.74,3569.45) ""(2710.74,3569.45) ""(2710.74,3569.45) ""(2710.74,3569.45) ""(2710.91,3568.86) ""(2710.91,3568.86) ""(2710.91,3568.86) ""(2710.91,3568.86) ""(2710.95,3574.59) ""(2710.95,3574.59) ""(2710.95,3574.59) ""(2710.95,3574.59) ""(2711.02,3561.62) ""(2711.02,3561.62) ""(2711.02,3561.62) ""(2711.02,3561.62) ""(2711.08,3567.47) ""(2711.08,3567.47) ""(2711.08,3567.47) ""(2711.08,3567.47) ""(2711.08,3567.47) ""(2711.08,3568.05) ""(2711.08,3568.05) ""(2711.08,3568.05) ""(2711.08,3568.05) ""(2711.15,3562.82) ""(2711.15,3562.82) ""(2711.15,3563.65) ""(2711.15,3563.65) ""(2711.15,3562.82) ""(2711.15,3562.82) ""(2711.15,3563.65) ""(2711.15,3563.65) ""(2711.15,3563.65) ""(2711.29,3554.59) ""(2711.29,3554.59) ""(2711.29,3554.59) ""(2711.29,3554.59) ""(2712.36,3574.12) ""(2712.36,3574.12) ""(2712.36,3574.12) ""(2712.36,3574.12) ""(2712.89,3555.66) ""(2712.89,3555.66) ""(2712.89,3555.66) ""(2712.89,3555.66) ""(2713.3,3573.52) ""(2713.3,3573.52) ""(2713.3,3573.52) ""(2713.3,3573.52) ""(2714.03,3556.6) ""(2714.03,3556.6) ""(2714.03,3556.6) ""(2714.03,3556.6) ""(2714.3,3572.65) ""(2714.3,3572.65) ""(2714.3,3572.65) ""(2714.3,3572.65) ""(2715.04,3557.54) ""(2715.04,3557.54) ""(2715.04,3557.54) ""(2715.04,3557.54) ""(2715.17,3571.58) ""(2715.17,3571.58) ""(2715.17,3571.58) ""(2715.17,3571.58) ""(2716.04,3558.81) ""(2716.04,3558.81) ""(2716.04,3558.81) ""(2716.04,3558.81) ""(2716.24,3569.98) ""(2716.24,3569.98) ""(2716.24,3569.98) ""(2716.24,3569.98) ""(2716.84,3560.48) ""(2716.84,3560.48) ""(2716.84,3560.48) ""(2716.84,3560.48) ""(2717.04,3568.5) ""(2717.04,3568.5) ""(2717.04,3568.5) ""(2717.04,3568.5) ""(2717.31,3561.82) ""(2717.31,3561.82) ""(2717.31,3561.82) ""(2717.31,3561.82) ""(2717.45,3567.43) ""(2717.45,3567.43) ""(2717.45,3567.43) ""(2717.45,3567.43) ""(2717.58,3563.35) ""(2717.58,3563.35) ""(2717.58,3566.1) ""(2717.58,3566.1) ""(2717.58,3563.35) ""(2717.58,3563.35) ""(2717.58,3566.1) ""(2717.58,3566.1) ""(2717.65,3564.76) ""(2717.65,3564.76) ""(2717.65,3564.76) ""(2717.65,3564.76) ""(2721.48,3562.04) ""(2721.48,3562.04) ""(2721.48,3564.86) ""(2721.48,3564.86) ""(2721.48,3562.04) ""(2721.48,3562.04) ""(2721.48,3564.86) ""(2721.48,3564.86) ""(2721.94,3560.4) ""(2721.94,3560.4) ""(2721.94,3560.4) ""(2721.94,3560.4) ""(2722.39,3567.42) ""(2722.39,3567.42) ""(2722.39,3567.42) ""(2722.39,3567.42) ""(2722.94,3558.58) ""(2722.94,3558.58) ""(2722.94,3558.58) ""(2722.94,3558.58) ""(2723.49,3568.87) ""(2723.49,3568.87) ""(2723.49,3568.87) ""(2723.49,3568.87) ""(2723.86,3576.23) ""(2723.86,3576.23) ""(2723.86,3576.23) ""(2723.86,3576.23) ""(2723.86,3576.23) ""(2723.86,3582.05) ""(2723.86,3582.05) ""(2723.86,3582.05) ""(2723.86,3582.05) ""(2723.86,3582.05) ""(2724.31,3556.76) ""(2724.31,3556.76) ""(2724.31,3556.76) ""(2724.31,3556.76) ""(2724.63,3575.46) ""(2724.63,3575.46) ""(2724.63,3582.82) ""(2724.63,3582.82) ""(2724.63,3575.46) ""(2724.63,3575.46) ""(2724.63,3575.46) ""(2724.63,3582.82) ""(2724.63,3582.82) ""(2724.63,3582.82) ""(2724.78,3582.82) ""(2724.78,3582.82) ""(2724.78,3582.82) ""(2724.78,3582.82) ""(2725.26,3582.71) ""(2725.26,3582.71) ""(2725.26,3582.71) ""(2725.26,3582.71) ""(2725.65,3582.51) ""(2725.65,3582.51) ""(2725.65,3582.51) ""(2725.65,3582.51) ""(2725.93,3582.26) ""(2725.93,3582.26) ""(2725.93,3582.26) ""(2725.93,3582.26) ""(2726.04,3582.11) ""(2726.04,3582.11) ""(2726.04,3582.11) ""(2726.04,3582.11) ""(2726.04,3582.11) ""(2726.12,3575.46) ""(2726.12,3575.46) ""(2726.12,3575.46) ""(2726.12,3575.46) ""(2726.12,3575.46) ""(2726.77,3554.85) ""(2726.77,3554.85) ""(2726.77,3554.85) ""(2726.77,3554.85) ""(2726.89,3576.17) ""(2726.89,3576.17) ""(2726.89,3576.17) ""(2726.89,3576.17) ""(2726.89,3576.17) ""(2726.95,3576.89) ""(2726.95,3576.89) ""(2726.95,3576.89) ""(2726.95,3576.89) ""(2727,3581.93) ""(2727,3581.93) ""(2727,3581.93) ""(2727,3581.93) ""(2727,3581.93) ""(2727.23,3577.8) ""(2727.23,3577.8) ""(2727.23,3577.8) ""(2727.23,3577.8) ""(2727.59,3561.13) ""(2727.59,3561.13) ""(2727.59,3561.13) ""(2727.59,3561.13) ""(2727.68,3560.04) ""(2727.68,3560.04) ""(2727.68,3560.04) ""(2727.68,3560.04) ""(2727.68,3578.71) ""(2727.68,3578.71) ""(2727.68,3578.71) ""(2727.68,3578.71) ""(2727.77,3558.67) ""(2727.77,3558.67) ""(2727.77,3558.67) ""(2727.77,3558.67) ""(2727.77,3562.13) ""(2727.77,3562.13) ""(2727.77,3562.13) ""(2727.77,3562.13) ""(2727.77,3571.61) ""(2727.77,3571.61) ""(2727.77,3571.61) ""(2727.77,3571.61) ""(2727.94,3582.43) ""(2727.94,3582.43) ""(2727.94,3582.43) ""(2727.94,3582.43) ""(2728.41,3579.8) ""(2728.41,3579.8) ""(2728.41,3579.8) ""(2728.41,3579.8) ""(2728.5,3563.32) ""(2728.5,3563.32) ""(2728.5,3563.32) ""(2728.5,3563.32) ""(2728.59,3557.49) ""(2728.59,3557.49) ""(2728.59,3557.49) ""(2728.59,3557.49) ""(2728.87,3554.21) ""(2728.87,3554.21) ""(2728.87,3554.21) ""(2728.87,3554.21) ""(2729.01,3582.87) ""(2729.01,3582.87) ""(2729.01,3582.87) ""(2729.01,3582.87) ""(2729.32,3563.86) ""(2729.32,3563.86) ""(2729.32,3563.86) ""(2729.32,3563.86) ""(2729.6,3556.67) ""(2729.6,3556.67) ""(2729.6,3556.67) ""(2729.6,3556.67) ""(2729.69,3580.62) ""(2729.69,3580.62) ""(2729.69,3580.62) ""(2729.69,3580.62) ""(2730.23,3583.2) ""(2730.23,3583.2) ""(2730.23,3583.2) ""(2730.23,3583.2) ""(2730.51,3580.9) ""(2730.51,3580.9) ""(2730.51,3580.9) ""(2730.51,3580.9) ""(2730.6,3572.52) ""(2730.6,3572.52) ""(2730.6,3572.52) ""(2730.6,3572.52) ""(2730.69,3564.77) ""(2730.69,3564.77) ""(2730.69,3564.77) ""(2730.69,3564.77) ""(2730.87,3556.3) ""(2730.87,3556.3) ""(2730.87,3556.3) ""(2730.87,3556.3) ""(2731.6,3553.84) ""(2731.6,3553.84) ""(2731.6,3553.84) ""(2731.6,3553.84) ""(2732.24,3581.26) ""(2732.24,3581.26) ""(2732.24,3581.26) ""(2732.24,3581.26) ""(2732.33,3556.03) ""(2732.33,3556.03) ""(2732.33,3556.03) ""(2732.33,3556.03) ""(2732.42,3565.32) ""(2732.42,3565.32) ""(2732.42,3565.32) ""(2732.42,3565.32) ""(2732.97,3573.7) ""(2732.97,3573.7) ""(2732.97,3573.7) ""(2732.97,3573.7) ""(2733.35,3556.09) ""(2733.35,3556.09) ""(2733.35,3556.09) ""(2733.35,3556.09) ""(2733.42,3583.48) ""(2733.42,3583.48) ""(2733.42,3583.48) ""(2733.42,3583.48) ""(2733.52,3553.75) ""(2733.52,3553.75) ""(2733.52,3553.75) ""(2733.52,3553.75) ""(2733.79,3580.99) ""(2733.79,3580.99) ""(2733.79,3580.99) ""(2733.79,3580.99) ""(2734.16,3556.2) ""(2734.16,3556.2) ""(2734.16,3556.2) ""(2734.16,3556.2) ""(2734.35,3553.87) ""(2734.35,3553.87) ""(2734.35,3553.87) ""(2734.35,3553.87) ""(2734.7,3574.61) ""(2734.7,3574.61) ""(2734.7,3574.61) ""(2734.7,3574.61) ""(2734.79,3566.5) ""(2734.79,3566.5) ""(2734.79,3566.5) ""(2734.79,3566.5) ""(2734.87,3583.27) ""(2734.87,3583.27) ""(2734.87,3583.27) ""(2734.87,3583.27) ""(2734.97,3580.53) ""(2734.97,3580.53) ""(2734.97,3580.53) ""(2734.97,3580.53) ""(2734.98,3553.96) ""(2734.98,3553.96) ""(2734.98,3553.96) ""(2734.98,3553.96) ""(2735.05,3556.33) ""(2735.05,3556.33) ""(2735.05,3556.33) ""(2735.05,3556.33) ""(2735.7,3575.61) ""(2735.7,3575.61) ""(2735.7,3575.61)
